(* Logix 5000 project; controller LinePLC1 vendor 1 type 14 code 154 rev 32.11; software revision 32.03 *)

TASK MainTask (continuous, watchdog 500 ms) : MainProgram

MODULES
   Local : vendor 1 type 14 code 154 (PointIO 0, rev 32.11)
      ISC_CAM_146 : ETHERNET-MODULE (Ethernet 192.168.1.146, rev 1.1, Output RPI 10 ms)   // isc-camxb145150d
           ISC_CAM_146:I.Data[1].5   // Status of photoeye Product Sensor 2 (Optional)
           ISC_CAM_146:I.Data[1].2   // Belt detected to move too slow (and not stopped)
           ISC_CAM_146:I.Data[13].0   // Parameter read succesfully
           ISC_CAM_146:I.Data[14]   // Parameter data register High Word
           ISC_CAM_146:I.Data[15]   // Parameter data register Low Word
           ISC_CAM_146:I.Data[1].0   // Line controller PLC indicated the drive motor is running, but the encoder does not detect motion
           ISC_CAM_146:I.Data[1].1   // Line controller PLC indicates the drive motor is off, but the encoder detects belt motion
           ISC_CAM_146:I.Data[1].10   // Too much or too low voltage from power supply
           ISC_CAM_146:I.Data[1].11   // Too much or too little current draw (indicates short or cable disconnected)
           ISC_CAM_146:I.Data[1].7   // Peg sensor blocked continuously with belt moving
           ISC_CAM_146:I.Data[1].3   // Belt detected to move too fast
           ISC_CAM_146:I.Data[1].4   // Status of photoeye Product Sensor 1
           ISC_CAM_146:I.Data[1].6   // Status of photoeye Product Sensor 3 (Optional)
           ISC_CAM_146:I.Data[1].8   // Peg not seen while expected
           ISC_CAM_146:I.Data[20]   // ActivationCount MSW - Cumulative number of activations divert zone 0
           ISC_CAM_146:I.Data[22]   // ActivationCount MSW - Cumulative number of activations divert zone 1
           ISC_CAM_146:I.Data[24]   // ActivationCount MSW - Cumulative number of activations divert zone 2
           ISC_CAM_146:I.Data[3]   // ProductsOnBelt - Count of current products on the belt (Optional in V1 scope)
           ISC_CAM_146:I.Data[0].1   // SystemReady
           ISC_CAM_146:I.Data[13]   // Parameter Status
           ISC_CAM_146:I.Data[18]   // BeltTravelDistance MSW
           ISC_CAM_146:I.Data[19]   // BeltTravelDistance LSW
           ISC_CAM_146:I.Data[30]   // GapToSmallCount MSW - Cumulative number a too small gap was detected
           ISC_CAM_146:I.Data[13].3   // Parameter value is out of range
           ISC_CAM_146:I.Data[13].2   // Parameter number not exist or read only
           ISC_CAM_146:I.Data[1].9   // Gap for next product
           ISC_CAM_146:I.Data[10]   // Uptime LSW - Time since the ISC is powered on
           ISC_CAM_146:I.Data[12]   // Parameter number feedback
           ISC_CAM_146:I.Data[13].1   // Parameter write succesfully
           ISC_CAM_146:I.Data[9]   // Uptime MSW - Time since the ISC is powered on
           ISC_CAM_146:I.Data[0].8   // EncoderStatus
           ISC_CAM_146:I.Data[21]   // ActivationCount LSW
           ISC_CAM_146:I.Data[16]   // BeltRunTime MSW
           ISC_CAM_146:I.Data[1].12   // IO-Link error port C0
           ISC_CAM_146:I.Data[1].13   // IO-Link error port C1
           ISC_CAM_146:I.Data[1].14   // IO-Link error port C2
           ISC_CAM_146:I.Data[1].15   // IO-Link error port C3
           ISC_CAM_146:I.Data[27]   // ProductCount LSW
           ISC_CAM_146:I.Data[34]   // PeakAcceleration
           ISC_CAM_146:I.Data[17]   // BeltRunTime LSW
           ISC_CAM_146:I.Data[1]   // Fault Code Word 1
           ISC_CAM_146:I.Data[2]   // Fault Code Word 2
           ISC_CAM_146:I.Data[0]   // Status
           ISC_CAM_146:I.Data[5]   // BeltSpeed - Current speed of the belt
           ISC_CAM_146:I.Data[6]   // BeltAcceleration - Acceleration speed of the belt
           ISC_CAM_146:I.Data[7]   // IOStatus - Active status of all inputs connected
           ISC_CAM_146:I.Data[0].0   // Life_Bit
           ISC_CAM_146:I.Data[32]   // FaultCount
           ISC_CAM_146:I.Data[29]   // StartStops LSW
           ISC_CAM_146:I.Data[23]   // ActivationCount LSW
           ISC_CAM_146:I.Data[25]   // ActivationCount LSW
           ISC_CAM_146:I.Data[33]   // MaxBeltSpeed
           ISC_CAM_146:I.Data[4]   // Troughput - Products per time unit on DPE (Optional in V1 scope)
           ISC_CAM_146:I.Data[28]   // StartStops MSW - Cumulative number of start stops of the belt
           ISC_CAM_146:I.Data[26]   // ProductCount MSW - Cumulative number of products on the belt
           ISC_CAM_146:I.Data[31]   // GapToSmallCount LSW
           ISC_CAM_146:I.Data[35]   // PeakDecceleration
           ISC_CAM_146:I.Data[0].4   // Error
           ISC_CAM_146:O.Data[1]   // Divert destination of the next product that will be arriving on the belt
           ISC_CAM_146:O.Data[2]   // RunMode
           ISC_CAM_146:O.Data[13]   // Read/Whrite Parameter
           ISC_CAM_146:O.Data[0].1   // BeltRunning
           ISC_CAM_146:O.Data[7]   // DestinationEnableDisable
           ISC_CAM_146:O.Data[3]   // ProductCountExit0
           ISC_CAM_146:O.Data[13].1   // Whrite Parameter
           ISC_CAM_146:O.Data[4]   // ProductCountExit1
           ISC_CAM_146:O.Data[0]   // Status
           ISC_CAM_146:O.Data[5]   // ProductCountExit2
           ISC_CAM_146:O.Data[0].0   // Life_Bit
           ISC_CAM_146:O.Data[12]   // Parameter number
           ISC_CAM_146:O.Data[13].0   // Read Parameter
           ISC_CAM_146:O.Data[14]   // Parameter Data MSW
           ISC_CAM_146:O.Data[0].7   // Reset_Error
           ISC_CAM_146:O.Data[15]   // Parameter Data LSW
           ISC_CAM_146:O.Data[6]   // ProductCountExit3
      ISC_CAM_145 : ETHERNET-MODULE (Ethernet 192.168.1.145, rev 1.1, Output RPI 10 ms)   // isc-camxb145150d
           ISC_CAM_145:I.Data[13].0   // Parameter read succesfully
           ISC_CAM_145:I.Data[14]   // Parameter data register High Word
           ISC_CAM_145:I.Data[15]   // Parameter data register Low Word
           ISC_CAM_145:I.Data[1].0   // Line controller PLC indicated the drive motor is running, but the encoder does not detect motion
           ISC_CAM_145:I.Data[1].1   // Line controller PLC indicates the drive motor is off, but the encoder detects belt motion
           ISC_CAM_145:I.Data[1].10   // Too much or too low voltage from power supply
           ISC_CAM_145:I.Data[1].11   // Too much or too little current draw (indicates short or cable disconnected)
           ISC_CAM_145:I.Data[1].2   // Belt detected to move too slow (and not stopped)
           ISC_CAM_145:I.Data[1].3   // Belt detected to move too fast
           ISC_CAM_145:I.Data[1].4   // Status of photoeye Product Sensor 1
           ISC_CAM_145:I.Data[1].5   // Status of photoeye Product Sensor 2 (Optional)
           ISC_CAM_145:I.Data[1].6   // Status of photoeye Product Sensor 3 (Optional)
           ISC_CAM_145:I.Data[1].7   // Peg sensor blocked continuously with belt moving
           ISC_CAM_145:I.Data[1].8   // Peg not seen while expected
           ISC_CAM_145:I.Data[20]   // ActivationCount MSW - Cumulative number of activations divert zone 0
           ISC_CAM_145:I.Data[22]   // ActivationCount MSW - Cumulative number of activations divert zone 1
           ISC_CAM_145:I.Data[13]   // Parameter Status
           ISC_CAM_145:I.Data[24]   // ActivationCount MSW - Cumulative number of activations divert zone 2
           ISC_CAM_145:I.Data[27]   // ProductCount LSW
           ISC_CAM_145:I.Data[3]   // ProductsOnBelt - Count of current products on the belt (Optional in V1 scope)
           ISC_CAM_145:I.Data[13].3   // Parameter value is out of range
           ISC_CAM_145:I.Data[34]   // PeakAcceleration
           ISC_CAM_145:I.Data[13].2   // Parameter number not exist or read only
           ISC_CAM_145:I.Data[18]   // BeltTravelDistance MSW
           ISC_CAM_145:I.Data[19]   // BeltTravelDistance LSW
           ISC_CAM_145:I.Data[30]   // GapToSmallCount MSW - Cumulative number a too small gap was detected
           ISC_CAM_145:I.Data[0].0   // Life_Bit
           ISC_CAM_145:I.Data[0].1   // SystemReady
           ISC_CAM_145:I.Data[5]   // BeltSpeed - Current speed of the belt
           ISC_CAM_145:I.Data[0]   // Status
           ISC_CAM_145:I.Data[32]   // FaultCount
           ISC_CAM_145:I.Data[1].9   // Gap for next product
           ISC_CAM_145:I.Data[10]   // Uptime LSW - Time since the ISC is powered on
           ISC_CAM_145:I.Data[12]   // Parameter number feedback
           ISC_CAM_145:I.Data[13].1   // Parameter write succesfully
           ISC_CAM_145:I.Data[9]   // Uptime MSW - Time since the ISC is powered on
           ISC_CAM_145:I.Data[0].8   // EncoderStatus
           ISC_CAM_145:I.Data[16]   // BeltRunTime MSW
           ISC_CAM_145:I.Data[17]   // BeltRunTime LSW
           ISC_CAM_145:I.Data[1].12   // IO-Link error port C0
           ISC_CAM_145:I.Data[1].13   // IO-Link error port C1
           ISC_CAM_145:I.Data[1].14   // IO-Link error port C2
           ISC_CAM_145:I.Data[1].15   // IO-Link error port C3
           ISC_CAM_145:I.Data[21]   // ActivationCount LSW
           ISC_CAM_145:I.Data[23]   // ActivationCount LSW
           ISC_CAM_145:I.Data[25]   // ActivationCount LSW
           ISC_CAM_145:I.Data[1]   // Fault Code Word 1
           ISC_CAM_145:I.Data[31]   // GapToSmallCount LSW
           ISC_CAM_145:I.Data[2]   // Fault Code Word 2
           ISC_CAM_145:I.Data[4]   // Troughput - Products per time unit on DPE (Optional in V1 scope)
           ISC_CAM_145:I.Data[6]   // BeltAcceleration - Acceleration speed of the belt
           ISC_CAM_145:I.Data[7]   // IOStatus - Active status of all inputs connected
           ISC_CAM_145:I.Data[0].4   // Error
           ISC_CAM_145:I.Data[26]   // ProductCount MSW - Cumulative number of products on the belt
           ISC_CAM_145:I.Data[29]   // StartStops LSW
           ISC_CAM_145:I.Data[28]   // StartStops MSW - Cumulative number of start stops of the belt
           ISC_CAM_145:I.Data[33]   // MaxBeltSpeed
           ISC_CAM_145:I.Data[35]   // PeakDecceleration
           ISC_CAM_145:O.Data[13]   // Read/Whrite Parameter
           ISC_CAM_145:O.Data[1]   // Divert destination of the next product that will be arriving on the belt
           ISC_CAM_145:O.Data[12]   // Parameter number
           ISC_CAM_145:O.Data[0].1   // BeltRunning
           ISC_CAM_145:O.Data[13].1   // Whrite Parameter
           ISC_CAM_145:O.Data[0].7   // Reset_Error
           ISC_CAM_145:O.Data[2]   // RunMode
           ISC_CAM_145:O.Data[7]   // DestinationEnableDisable
           ISC_CAM_145:O.Data[3]   // ProductCountExit0
           ISC_CAM_145:O.Data[0]   // Status
           ISC_CAM_145:O.Data[0].0   // Life_Bit
           ISC_CAM_145:O.Data[4]   // ProductCountExit1
           ISC_CAM_145:O.Data[5]   // ProductCountExit2
           ISC_CAM_145:O.Data[6]   // ProductCountExit3
           ISC_CAM_145:O.Data[13].0   // Read Parameter
           ISC_CAM_145:O.Data[14]   // Parameter Data MSW
           ISC_CAM_145:O.Data[15]   // Parameter Data LSW
      Discrete_IO : Embedded (PointIO 1, rev 32.11, Output RPI 20 ms)
      DO_002 : 1734-OB8E (PointIO 3, rev 3.1, Output RPI 20 ms)
      DO_001 : 1734-OB8E (PointIO 2, rev 3.1, Output RPI 20 ms)
END_MODULES

TYPE dt_Constant :   // Constants
STRUCT
   ParameterNr : DINT;
   RecipeNr : DINT;
END_STRUCT
END_TYPE

TYPE dt_DTL :   // An operand of data type DTL has a length of 12 bytes and stores date and time information in a predefined structure.
STRUCT
   Year : INT;   // Year - 1970 to 2262
   Month : SINT;   // Month - 0 to 12
   Day : SINT;   // Day - 1 to 31
   Weekday : SINT;   // Weekday - 1(Sunday) to 7(Saturday) The weekday is not considered in the value entry.
   Hour : SINT;   // Hour - 0 to 23
   Minute : SINT;   // Minute - 0 to 59
   Second : SINT;   // Second - 0 to 59
   Nanosecond : DINT;   // Nanosecond - 0 to 999999999
END_STRUCT
END_TYPE

TYPE dt_General_HMI :   // General HMI
STRUCT
   GeneralDateTimePLC : dt_DTL;
   GeneralHmiSNPointer : INT[5];
   GeneralHMIScreenNumber : INT;
   GeneralFaultBits : INT[8];
   GeneralFaultGroupBits : INT;
   GeneralFault : BOOL;
   GeneralAlarmBtnCol : INT;
   GeneralResetBtnCmd : BOOL;
   AlarmBtnCol : INT;
   MaintenanceBtnCol : INT;
END_STRUCT
END_TYPE

TYPE dt_Global :   // Global
STRUCT
   InitRecipe : BOOL;
   MyMODE : DINT;
   returnValue : INT;
   myState : BOOL[1024];
END_STRUCT
END_TYPE

TYPE dt_ISC_CAM_Alarms :
STRUCT
   CommsAlarm : BOOL;   // Communication to ISC not healthy.
   Fault8Alarm : BOOL;   // Peg not seen when expected
   Fault9Alarm : BOOL;   // Gap for next product
   Fault10Alarm : BOOL;   // Too much or too low voltage from power supply
   Fault11Alarm : BOOL;   // IO Current fault, input too high or too low (indicates short or cable disconnected)
   Fault12Alarm : BOOL;   // IO-Link error port C0
   Fault13Alarm : BOOL;   // IO-Link error port C1
   Fault14Alarm : BOOL;   // IO-Link error port C2
   Fault15Alarm : BOOL;   // IO-Link error port C3
   Fault0Alarm : BOOL;   // Line controller PLC indicated the motor is running. But the encoder does not detect motion
   Fault1Alarm : BOOL;   // Peg sensor blocked continuously with belt moving
   Fault2Alarm : BOOL;   // Status of photoeye Product Sensor 3 (optional)
   Fault3Alarm : BOOL;   // Status of photoeye Product Sensor 2 (optional)
   Fault4Alarm : BOOL;   // Status of photoeye Product Sensor 1
   Fault5Alarm : BOOL;   // Belt detected to move too fast
   Fault6Alarm : BOOL;   // Belt detected to move too slow (and not stopped)
   Fault7Alarm : BOOL;   // Line controller PLC indicates the drive motor is off, but the encoder detects belt motion
END_STRUCT
END_TYPE

TYPE dt_ISC_CAM_Comm :
STRUCT
   DataIn : DINT[48];
   TempDataIn : dt_ISCCAM_IO_IN;
   DataOut : DINT[16];
   TempDataOut : dt_ISCCAM_IO_OUT;
   CommHealthy : BOOL;
   CommStatus : INT;
   ConnectionStatus : INT;
   Comms : FB_ISCCAM_Comm;
   Alarms : FB_ISC_Alarms;
   IOConversion : FB_IO_Conversion;
   tempIn : DINT[48];
   tempOut : DINT[48];
END_STRUCT
END_TYPE

TYPE dt_ISC_CAM_FaultCodes :
STRUCT
   FaultCode8 : BOOL;   // Peg not seen when expected
   FaultCode9 : BOOL;   // Gap for next product
   FaultCode10 : BOOL;   // Too much or too low voltage from power supply
   FaultCode11 : BOOL;   // IO Current fault, input too high or too low (indicates short or cable disconnected)
   FaultCode12 : BOOL;   // IO-Link error port C0
   FaultCode13 : BOOL;   // IO-Link error port C1
   FaultCode14 : BOOL;   // IO-Link error port C2
   FaultCode15 : BOOL;   // IO-Link error port C3
   FaultCode0 : BOOL;   // Line controller PLC indicated the motor is running. But the encoder does not detect motion
   FaultCode1 : BOOL;   // Peg sensor blocked continuously with belt moving
   FaultCode2 : BOOL;   // Status of photoeye Product Sensor 3 (optional)
   FaultCode3 : BOOL;   // Status of photoeye Product Sensor 2 (optional)
   FaultCode4 : BOOL;   // Status of photoeye Product Sensor 1
   FaultCode5 : BOOL;   // Belt detected to move too fast
   FaultCode6 : BOOL;   // Belt detected to move too slow (and not stopped)
   FaultCode7 : BOOL;   // Line controller PLC indicates the drive motor is off, but the encoder detects belt motion
   FaultCode24 : BOOL;
   FaultCode25 : BOOL;
   FaultCode26 : BOOL;
   FaultCode27 : BOOL;
   FaultCode28 : BOOL;
   FaultCode29 : BOOL;
   FaultCode30 : BOOL;
   FaultCode31 : BOOL;
   FaultCode16 : BOOL;
   FaultCode17 : BOOL;
   FaultCode18 : BOOL;
   FaultCode19 : BOOL;
   FaultCode20 : BOOL;
   FaultCode21 : BOOL;
   FaultCode22 : BOOL;
   FaultCode23 : BOOL;
END_STRUCT
END_TYPE

TYPE dt_ISC_CAM_IOStatus :
STRUCT
   IOStatus8 : BOOL;
   IOStatus9 : BOOL;
   IOStatus10 : BOOL;
   IOStatus11 : BOOL;
   IOStatus12 : BOOL;
   IOStatus13 : BOOL;
   IOStatus14 : BOOL;
   IOStatus15 : BOOL;
   IOStatus0 : BOOL;
   IOStatus1 : BOOL;   // Product sensor
   IOStatus2 : BOOL;   // Peg sensor diver 1 (AIM only)
   IOStatus3 : BOOL;   // Valve divert 1
   IOStatus4 : BOOL;   // Peg sensor diver 2 (AIM only)
   IOStatus5 : BOOL;   // Valve divert 2
   IOStatus6 : BOOL;   // Discrete diver signal
   IOStatus7 : BOOL;
END_STRUCT
END_TYPE

TYPE dt_ISC_CAM_Maintenance :
STRUCT
   Threshold : DINT[16];
   Maintenance : FB_ISC_CAM_Maintenance[16];
END_STRUCT
END_TYPE

TYPE dt_ISC_CAM_Receive :
STRUCT
   W0 : dt_ISC_CAM_RECEIVE_W0;
   W1W2_Faultcode : DINT;
   W3_ProductsOnBelt : INT;
   W4_ThroughPut : INT;
   W5_Beltspeed : INT;
   W6_BeltAcceleration : INT;
   W7_IOStatus : INT;
   W8 : INT;
   W9_PowerOn_MSW : INT;
   W10_PowerOn_LSW : INT;
   W11 : INT;
   W12_ParameterNumberFeedback : INT;
   W13 : dt_ISC_CAM_RECEIVE_W13;
   W14_ParameterDataRegisterHighWord : INT;
   W15_ParameterDataRegisterLowWor : INT;
   W16_BeltRunTime_MSW : INT;
   W17_BeltRunTime_LSW : INT;
   W18BeltTravelDistance_MSW : INT;
   W19BeltTravelDistance_LSW : INT;
   W20ActivationCount_Zone0_MSW : INT;
   W21ActivationCount_Zone0_LSW : INT;
   W22ActivationCount_Zone1_MSW : INT;
   W23ActivationCount_Zone1_LSW : INT;
   W24ActivationCount_Zone2_MSW : INT;
   W25ActivationCount_Zone2_LSW : INT;
   W26ProductCount_MSW : INT;
   W27ProductCount_LSW : INT;
   W28StartStops_MSW : INT;
   W29StartStops_LSW : INT;
   W30GapToSmallCount_MSW : INT;
   W31GapToSmallCount_LSW : INT;
   W32FaultCount : INT;
   W33MaxBeltSpeed : INT;
   W34PeakAcceleration : INT;
   W35PeakDeceleration : INT;
END_STRUCT
END_TYPE

TYPE dt_ISC_CAM_RECEIVE_W0 :
STRUCT
   Bit8 : BOOL;
   Bit9 : BOOL;
   Bit10 : BOOL;
   Bit11 : BOOL;
   Bit12 : BOOL;
   Bit13 : BOOL;
   Bit14 : BOOL;
   Bit15 : BOOL;
   Bit0LifeBit : BOOL;
   Bit1SystemReady : BOOL;
   Bit2 : BOOL;
   Bit3 : BOOL;
   Bit4Error : BOOL;
   Bit5 : BOOL;
   Bit6 : BOOL;
   Bit7 : BOOL;
END_STRUCT
END_TYPE

TYPE dt_ISC_CAM_RECEIVE_W13 :
STRUCT
   Bit8 : BOOL;
   Bit9 : BOOL;
   Bit10 : BOOL;
   Bit11 : BOOL;
   Bit12 : BOOL;
   Bit13 : BOOL;
   Bit14 : BOOL;
   Bit15 : BOOL;
   Bit0ParameterReadSuccesful : BOOL;
   Bit1ParameterWriteSucceful : BOOL;
   Bit2ParameterNumberNotExistOrReadOnly : BOOL;
   Bit3ParameterValueIsOutOfRange : BOOL;
   Bit4 : BOOL;
   Bit5 : BOOL;
   Bit6 : BOOL;
   Bit7 : BOOL;
END_STRUCT
END_TYPE

TYPE dt_ISC_CAM_Send :
STRUCT
   W0 : dt_ISC_CAM_SEND_W0;
   W1_DivertDestination : INT;
   W2_RunMode : INT;
   W3_ProductCountExit0 : INT;
   W4_ProductCountExit1 : INT;
   W5_ProductCountExit2 : INT;
   W6_ProductCountExit3 : INT;
   W7 : dt_ISCCAM_Send_W7;
   W8 : INT;
   W9 : INT;
   W10 : INT;
   W11 : INT;
   W12_ParameterNumberForReadWriteAccess : INT;
   W13 : dt_ISCCAM_Send_W13;
   W14_ParameterDataRegisterHighWord : INT;
   W15_ParameterDataRegisterLowWord : INT;
END_STRUCT
END_TYPE

TYPE dt_ISC_CAM_SEND_W0 :
STRUCT
   Bit8 : BOOL;
   Bit9 : BOOL;
   Bit10 : BOOL;
   Bit11 : BOOL;
   Bit12 : BOOL;
   Bit13ProductsFromInfeed2 : BOOL;
   Bit14 : BOOL;
   Bit15 : BOOL;
   Bit0LifeBit : BOOL;
   Bit1MotorRunning : BOOL;
   Bit2 : BOOL;
   Bit3 : BOOL;
   Bit4 : BOOL;
   Bit5 : BOOL;
   Bit6 : BOOL;
   Bit7Reset_Error : BOOL;
END_STRUCT
END_TYPE

TYPE dt_ISC_CAM_Status :
STRUCT
   Status : dt_ISCCAM_Stat;
   Command : dt_ISCCAM_Cmd;
   Parameter : dt_ISCCAM_Parameter;
   DataCollection : dt_ISCCAM_Datacollection;
END_STRUCT
END_TYPE

TYPE dt_ISCCAM :   // ISC-CAM
STRUCT
   Command : dt_ISCCAM_Cmd;
   Status : dt_ISCCAM_Stat;
   Parameter : dt_ISCCAM_Parameter;
   Datacollection : dt_ISCCAM_Datacollection;
END_STRUCT
END_TYPE

TYPE dt_ISCCAM_Cmd :   // ISC-CAM Cmd
STRUCT
   LifeBit : BOOL;   // Lifebit
   Reset_Error : BOOL;   // Reset error
   MotorRunning : BOOL;   // Motor running
   ProductsFromInfeed2 : BOOL;   // Products from infeed 2
   AssignDestination : INT;   // Assign destination
   ExternalModel : BOOL;   // External model
   Exit1BalancingSet : INT;   // Set balancing exit 1
   Exit2BalancingSet : INT;   // Set balancing exit 2
   Exit3BalancingSet : INT;   // Set balancing exit 3
   EndBalancingSet : INT;   // Set balancing end
   DES_Enable1 : BOOL;   // Enable destination 1
   DES_Enable2 : BOOL;   // Enable destination 2
   DES_Enable3 : BOOL;   // Enable destination 3
END_STRUCT
END_TYPE

TYPE dt_ISCCAM_Datacollection :   // ISC-CAM Datacollection
STRUCT
   BeltRunTime : DINT;   // Cumulative time the belt is moving [min]
   BeltTravelDistance : DINT;   // Cumulative distance the belt has traveled [m]
   ActivationCount_Zone_0 : DINT;   // Cumulative number of activations divert zone 0
   ActivationCount_Zone_1 : DINT;   // Cumulative number of activations divert zone 1
   ActivationCount_Zone_2 : DINT;   // Cumulative number of activations divert zone 2
   ProductCount : DINT;   // Cumulative number of products on the belt
   StartStops : DINT;   // Cumulative number of start stops of the belt
   GapToSmallCount : DINT;   // Cumulative number a too small gap was detected
   FaultCount : INT;   // A counter that keeps track of how many faults were detected
   MaxBeltSpeed : INT;   // The maximum belt speed that has been detected [m/min]
   PeakAcceleration : INT;   // Peak acceleration [m/min2]
   PeakDecceleration : INT;   // Peak decceleration [m/min2]
END_STRUCT
END_TYPE

TYPE dt_ISCCAM_FaultCode :   // ISC-CAM Fault Code
STRUCT
   FaultCode : BOOL[32];   // FaultCode
   FaultCode00 : BOOL;   // Line controller PLC indicated the drive motor is running, but the encoder does not detect motion
   FaultCode01 : BOOL;   // Line controller PLC indicates the drive motor is off, but the encoder detects belt motion
   FaultCode02 : BOOL;   // Belt detected to move too slow (and not stopped)
   FaultCode03 : BOOL;   // Belt detected to move too fast
   FaultCode04 : BOOL;   // Status of photoeye Product Sensor 1
   FaultCode05 : BOOL;   // Status of photoeye Product Sensor 2 (Optional)
   FaultCode06 : BOOL;   // Status of photoeye Product Sensor 3 (Optional)
   FaultCode07 : BOOL;   // Peg sensor blocked continuously with belt moving
   FaultCode08 : BOOL;   // Peg not seen when expected
   FaultCode09 : BOOL;   // Gap for next product
   FaultCode10 : BOOL;   // Too much or too low voltage from power supply
   FaultCode11 : BOOL;   // IO Current fault. Input too high or too low (indicates short or cable disconnected)
   FaultCode12 : BOOL;   // IO-Link error port C0
   FaultCode13 : BOOL;   // IO-Link error port C1
   FaultCode14 : BOOL;   // IO-Link error port C2
   FaultCode15 : BOOL;   // IO-Link error port C3
   FaultCode16 : BOOL;
   FaultCode17 : BOOL;
   FaultCode18 : BOOL;
   FaultCode19 : BOOL;
   FaultCode20 : BOOL;
   FaultCode21 : BOOL;
   FaultCode22 : BOOL;
   FaultCode23 : BOOL;
   FaultCode24 : BOOL;
   FaultCode25 : BOOL;
   FaultCode26 : BOOL;
   FaultCode27 : BOOL;
   FaultCode28 : BOOL;
   FaultCode29 : BOOL;
   FaultCode30 : BOOL;
   FaultCode31 : BOOL;
END_STRUCT
END_TYPE

TYPE dt_ISCCAM_HMI :   // Machine 001 HMI
STRUCT
   FaultBits : dt_ISC_CAM_Alarms;
   Fault : BOOL;
   MaintenanceCounters : dt_ISCCAM_Maintenance;
END_STRUCT
END_TYPE

TYPE dt_ISCCAM_IO_IN :
STRUCT
   W1 : DINT;
   W2 : DINT;
   W3 : DINT;
   W4 : DINT;
   W5 : DINT;
   W6 : DINT;
   W7 : DINT;
   W8 : DINT;
   W9 : DINT;
   W10 : DINT;
   W11 : DINT;
   W12 : DINT;
   W13 : DINT;
   W14 : DINT;
   W15 : DINT;
   W16 : DINT;
   W17 : DINT;
   W18 : DINT;
   W19 : DINT;
   W20 : DINT;
   W21 : DINT;
   W22 : DINT;
   W23 : DINT;
   W24 : DINT;
   W25 : DINT;
   W26 : DINT;
   W27 : DINT;
   W28 : DINT;
   W29 : DINT;
   W30 : DINT;
   W31 : DINT;
   W32 : DINT;
   W33 : DINT;
   W34 : DINT;
   W35 : DINT;
   W36 : DINT;
   W37 : DINT;
   W38 : DINT;
   W39 : DINT;
   W40 : DINT;
   W41 : DINT;
   W42 : DINT;
   W43 : DINT;
   W44 : DINT;
   W45 : DINT;
   W46 : DINT;
   W47 : DINT;
   W48 : DINT;
END_STRUCT
END_TYPE

TYPE dt_ISCCAM_IO_OUT :
STRUCT
   W1 : DINT;
   W2 : DINT;
   W3 : DINT;
   W4 : DINT;
   W5 : DINT;
   W6 : DINT;
   W7 : DINT;
   W8 : DINT;
   W9 : DINT;
   W10 : DINT;
   W11 : DINT;
   W12 : DINT;
   W13 : DINT;
   W14 : DINT;
   W15 : DINT;
   W16 : DINT;
END_STRUCT
END_TYPE

TYPE dt_ISCCAM_Maintenance :
STRUCT
   Counters : dt_ISCCAM_MaintenanceCounter[16];
END_STRUCT
END_TYPE

TYPE dt_ISCCAM_MaintenanceCounter :
STRUCT
   Reset : BOOL;   // Reset warning
   WarningBit : BOOL;   // Warning active
   MaintenanceThreshold : DINT;   // Threshold to create warning
   MaintenanceCountUntilNextMaintenance : DINT;   // Count until next maintenance
END_STRUCT
END_TYPE

TYPE dt_ISCCAM_Parameter :   // ISC-CAM Parameter
STRUCT
   Cmd : dt_ISCCAM_Parameter_Cmd;
   Stat : dt_ISCCAM_Parameter_Stat;
END_STRUCT
END_TYPE

TYPE dt_ISCCAM_Parameter_Cmd :   // ISC-CAM Parameter Cmd
STRUCT
   ParameterNumber : INT;   // Parameter number f or read / write access.
   ParameterData : DINT;   // Parameter data f or write access.
   ReadTrigger : BOOL;   // Read trigger.
   WriteTrigger : BOOL;   // Write trigger.
END_STRUCT
END_TYPE

TYPE dt_ISCCAM_Parameter_Stat :   // ISC-CAM Parameter Stat
STRUCT
   ParameterNumber : INT;   // Parameter number feedback
   ParameterData : DINT;   // Parameter data
   ParameterReadSuccessfully : BOOL;   // Parameter read successfully
   ParameterWriteSuccessfully : BOOL;   // Parameter write successfully
   ParameterNumberNotExistReadOnly : BOOL;   // Parameter number does not exist or is read only
   ParameterValueOutOfRange : BOOL;   // Parameter value out of range
END_STRUCT
END_TYPE

TYPE dt_ISCCAM_PI :   // ISC-CAM PI
STRUCT
   Status : dt_ISCCAM_PI_Status;
   DataCollection1 : dt_ISCCAM_PI_DataCollection_1;
   DataCollection2 : dt_ISCCAM_PI_DataCollection_2;
END_STRUCT
END_TYPE

TYPE dt_ISCCAM_PI_DataCollection_1 :   // ISC-CAM PI Data Collection 1
STRUCT
   BeltRunTime_MSW : INT;   // Cumulative time the belt is moving [min] HiWord
   BeltRunTime_LSW : INT;   // Cumulative time the belt is moving [min] LoWord
   BeltTravelDistance_MSW : INT;   // Cumulative distance the belt has traveled [m] HiWord
   BeltTravelDistance_LSW : INT;   // Cumulative distance the belt has traveled [m] LoWord
   ActivationCount_Zone0_MSW : INT;   // Cumulative number of activations divert zone 0 HiWord
   ActivationCount_Zone0_LSW : INT;   // Cumulative number of activations divert zone 0 LoWord
   ActivationCount_Zone1_MSW : INT;   // Cumulative number of activations divert zone 1 HiWord
   ActivationCount_Zone1_LSW : INT;   // Cumulative number of activations divert zone 1 LoWord
   ActivationCount_Zone2_MSW : INT;   // Cumulative number of activations divert zone 2 HiWord
   ActivationCount_Zone2_LSW : INT;   // Cumulative number of activations divert zone 2 LoWord
   ProductCount_MSW : INT;   // Cumulative number of products on the belt HiWord
   ProductCount_LSW : INT;   // Cumulative number of products on the belt LoWord
   StartStops_MSW : INT;   // Cumulative number of start stops of the belt HiWord
   StartStops_LSW : INT;   // Cumulative number of start stops of the belt LoWord
   GapToSmallCount_MSW : INT;   // Cumulative number a too small gap was detected HiWord
   GapToSmallCount_LSW : INT;   // Cumulative number a too small gap was detected LoWord
END_STRUCT
END_TYPE

TYPE dt_ISCCAM_PI_DataCollection_2 :   // ISC-CAM PI Data Collection 2
STRUCT
   FaultCount : INT;   // A counter that keeps track of how many faults were detected
   MaxBeltSpeed : INT;   // The maximum belt speed that has been detected [m/min]
   PeakAcceleration : INT;   // Peak acceleration [m/min2]
   PeakDecceleration : INT;   // Peak decceleration [m/min2]
END_STRUCT
END_TYPE

TYPE dt_ISCCAM_PI_Status :   // ISC-CAM PI Status
STRUCT
   Life_Bit : BOOL;   // Life bit / Heartbeat / Watchdog
   SystemReady : BOOL;   // System Ready (no fault)
   W0b2 : BOOL;
   W0b3 : BOOL;
   Error : BOOL;   // Error in Machine
   W0b4 : BOOL;
   W0b5 : BOOL;
   W0b6 : BOOL;
   W0b7 : BOOL;
   EncoderStatus : BOOL;   // Belt encoder pulses
   W0b9 : BOOL;
   W0b10 : BOOL;
   W0b11 : BOOL;
   W0b12 : BOOL;
   W0b13 : BOOL;
   W0b14 : BOOL;
   W0b15 : BOOL;
END_STRUCT
END_TYPE

TYPE dt_ISCCAM_PO :   // ISC-CAM PO
STRUCT
   Command : dt_ISCCAM_PO_Command;
END_STRUCT
END_TYPE

TYPE dt_ISCCAM_PO_Command :   // ISC_CAM_PO_Command
STRUCT
   Life_Bit : BOOL;   // Life bit
   MotorRunning : BOOL;   // Motor is running
   W0b2 : BOOL;
   W0b3 : BOOL;
   W0b4 : BOOL;
   W0b5 : BOOL;
   W0b6 : BOOL;
   Reset_Error : BOOL;   // Reset all errors
   W0b8 : BOOL;
   W0b9 : BOOL;
   W0b10 : BOOL;
   W0b11 : BOOL;
   W0b12 : BOOL;
   ProductsFromInfeed2 : BOOL;   // Products from infeed 2
   W0b14 : BOOL;
   W0b15 : BOOL;
   Divert_destination : INT;   // Divert destination of the next product that will be arriving on the belt (external mode only)
   RunMode : INT;   // Internal mode [0] or external mode [1]
   ProductCountExit0 : INT;   // Number of products to exit (internal mode only)
   ProductCountExit1 : INT;   // Number of products to exit (internal mode only)
   ProductCountExit2 : INT;   // Number of products to exit (internal mode only)
   ProductCountExit3 : INT;   // Number of products to exit (internal mode only)
   Enable_exit_1 : BOOL;   // Destination Enable/Disable
   Enable_exit_2 : BOOL;   // Destination Enable/Disable
   Enable_exit_3 : BOOL;   // Destination Enable/Disable
   W7b3 : BOOL;
   W7b4 : BOOL;
   W7b5 : BOOL;
   W7b6 : BOOL;
   W7b7 : BOOL;
   W8 : INT;
   W9 : INT;
   W10 : INT;
   W11 : INT;
   Parameter_number_for_read_write_access : INT;   // Parameter number
   Read_Parameter : BOOL;   // Read parameter
   Write_Parameter : BOOL;   // Write parameter
   W13b2 : BOOL;
   W13b3 : BOOL;
   W13b4 : BOOL;
   W13b5 : BOOL;
   W13b6 : BOOL;
   W13b7 : BOOL;
   W13b8 : BOOL;
   W13b9 : BOOL;
   W13b10 : BOOL;
   W13b11 : BOOL;
   W13b12 : BOOL;
   W13b13 : BOOL;
   W13b14 : BOOL;
   W13b15 : BOOL;
   Parameter_data_register_High_Word : INT;   // Parameter Data MSW
   Parameter_data_register_Low_Word : INT;   // Parameter Data LSW
END_STRUCT
END_TYPE

TYPE dt_ISCCAM_Send_W13 :
STRUCT
   Bit8 : BOOL;
   Bit9 : BOOL;
   Bit10 : BOOL;
   Bit11 : BOOL;
   Bit12 : BOOL;
   Bit13 : BOOL;
   Bit14 : BOOL;
   Bit15 : BOOL;
   Bit0ReadParameter : BOOL;
   Bit1WriteParameter : BOOL;
   Bit2 : BOOL;
   Bit3 : BOOL;
   Bit4 : BOOL;
   Bit5 : BOOL;
   Bit6 : BOOL;
   Bit7 : BOOL;
END_STRUCT
END_TYPE

TYPE dt_ISCCAM_Send_W7 :
STRUCT
   Bit8 : BOOL;
   Bit9 : BOOL;
   Bit10 : BOOL;
   Bit11 : BOOL;
   Bit12 : BOOL;
   Bit13 : BOOL;
   Bit14 : BOOL;
   Bit15 : BOOL;
   Bit0EnableExit1 : BOOL;
   Bit1EnableExit2 : BOOL;
   Bit2EnableExit3 : BOOL;
   Bit3 : BOOL;
   Bit4 : BOOL;
   Bit5 : BOOL;
   Bit6 : BOOL;
   Bit7 : BOOL;
END_STRUCT
END_TYPE

TYPE dt_ISCCAM_Stat :   // ISC-CAM Stat
STRUCT
   LifeBit : BOOL;   // Lifebit
   SystemReady : BOOL;   // System ready
   Error : BOOL;   // Error
   FaultCode : dt_ISC_CAM_FaultCodes;   // Fault code
   ProductsOnBelt : INT;   // Products on belt
   Throughput : INT;   // Throughput
   BeltSpeed : INT;   // Belt speed
   BeltAcceleration : INT;   // Belt acceleration
   IOstatus : dt_ISC_CAM_IOStatus;   // IO status
   UpTime : DINT;   // Up time
   Alarms : dt_ISC_CAM_Alarms;
END_STRUCT
END_TYPE

TYPE dt_Rec_ISCCAM_Parameter :   // Recipe ISCCAM Parameter
STRUCT
   ID : INT;
   Description : STRING;
END_STRUCT
END_TYPE

TYPE dt_Rec_ISCCAM_Recipe :   // Recipe ISCCAM Recipe
STRUCT
   Header : dt_Rec_ISCCAM_Recipe_Header;
   Machine : dt_Rec_ISCCAM_Recipe_Parameter;
END_STRUCT
END_TYPE

TYPE dt_Rec_ISCCAM_Recipe_Header :   // Recipe ISCCAM Recipe
STRUCT
   Name : STRING;
   Number : DINT;
END_STRUCT
END_TYPE

TYPE dt_Rec_ISCCAM_Recipe_Parameter :   // Recipe ISCCAM Recipe Parameter
STRUCT
   ID : INT;   // Parameter ID.
   Name : STRING;   // Parameter Name.
   Description : STRING;   // Comment.
   Value : DINT;   // Parameter value.
END_STRUCT
END_TYPE

TYPE dt_Rec_M001_Recipe :   // Machine M001 Recipe
STRUCT
   Header : dt_Rec_ISCCAM_Recipe_Header;
   Machine_001 : dt_Rec_Machine_Recipe_Parameter;
END_STRUCT
END_TYPE

TYPE dt_Rec_M002_Recipe :
STRUCT
   Header : dt_Rec_ISCCAM_Recipe_Header;
   Machine_002 : dt_Rec_Machine_Recipe_Parameter;
END_STRUCT
END_TYPE

TYPE dt_Rec_Machine_Recipe_Parameter :
STRUCT
   Parameter : dt_Rec_ISCCAM_Recipe_Parameter[32];
END_STRUCT
END_TYPE

TYPE dt_Rec_Recipe :   // Recipe
STRUCT
   Header : dt_Rec_ISCCAM_Recipe_Header;
   M001 : dt_Rec_M001_Recipe;
   M002 : dt_Rec_M002_Recipe;
END_STRUCT
END_TYPE

TYPE dt_Recipe :   // Recipe
STRUCT
   ParameterList : dt_Rec_ISCCAM_Parameter[14];
   Recipe : dt_Rec_Recipe[4];
END_STRUCT
END_TYPE

ADD_ON_INSTRUCTION FB_2INT_To_DINT   (* revision 1.0, vendor INTRALOX *)
VAR_INPUT
   iINT_MSW : INT; {required}
   iINT_LSW : INT; {required}
END_VAR
VAR_OUTPUT
   qDINT : DINT; {access Read Only, required}
END_VAR
VAR
   sDINT_1 : DINT; {access None}
   sDINT_2 : DINT; {access None}
END_VAR

ROUTINE Logic   (* ladder *)
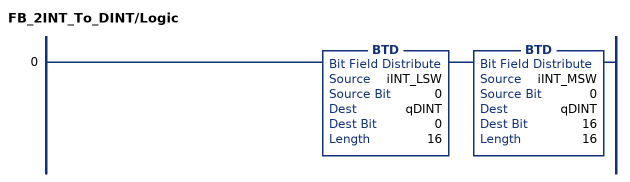
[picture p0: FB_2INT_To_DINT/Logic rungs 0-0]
   0: BTD(iINT_LSW,0,qDINT,0,16)BTD(iINT_MSW,0,qDINT,16,16);
END_ROUTINE
END_ADD_ON_INSTRUCTION

ADD_ON_INSTRUCTION FB_Auxiliary_Sensors   (* revision 1.0, vendor INTRALOX *)
VAR_INPUT
   iPressureSwitch : BOOL := 1; {required}
   iBeltElongationInfeed1 : BOOL := 1; {required}
   iBeltElongationInfeed2 : BOOL := 1; {required}
   iBeltElongationOutfeed1 : BOOL := 1; {required}
   iBeltElongationOutfeed2 : BOOL := 1; {required}
   iJamSensorInfeed : BOOL := 1; {required}
   iJamSensorOutfeed : BOOL := 1; {required}
   iBeltDisengagement : BOOL := 1; {required}
   iDebris : BOOL := 1; {required}
   iReset : BOOL := 1; {required}
END_VAR
VAR_IN_OUT
   oAlarms : BOOL[32]; {required}
END_VAR
VAR_INPUT
   iJamSensor1Time : DINT; {required}   // Time in ms to trigger Jam sensor fault
   iJamSensor2Time : DINT; {access None, required}   // Time in ms to trigger Jam sensor fault
   iBeltRunning : BOOL; {access None, required}   // Belt is running signal
END_VAR
VAR
   JamSensor1Timer : TIMER := (PRE := 2000); {access None}
   JamSensor2Timer : TIMER := (PRE := 2000); {access None}
END_VAR

ROUTINE Logic   (* ladder *)
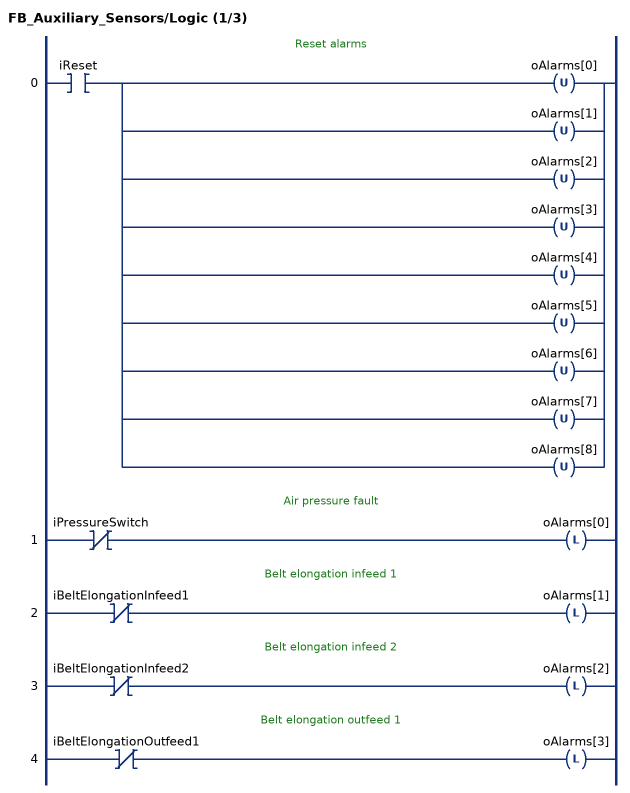
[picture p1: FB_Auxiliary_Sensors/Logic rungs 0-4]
   // Reset alarms
   0: XIC(iReset)[OTU(oAlarms[0]) ,OTU(oAlarms[1]) ,OTU(oAlarms[2]) ,OTU(oAlarms[3]) ,OTU(oAlarms[4]) ,OTU(oAlarms[5]) ,OTU(oAlarms[6]) ,OTU(oAlarms[7]) ,OTU(oAlarms[8]) ];
   // Air pressure fault
   1: XIO(iPressureSwitch)OTL(oAlarms[0]);
   // Belt elongation infeed 1
   2: XIO(iBeltElongationInfeed1)OTL(oAlarms[1]);
   // Belt elongation infeed 2
   3: XIO(iBeltElongationInfeed2)OTL(oAlarms[2]);
   // Belt elongation outfeed 1
   4: XIO(iBeltElongationOutfeed1)OTL(oAlarms[3]);
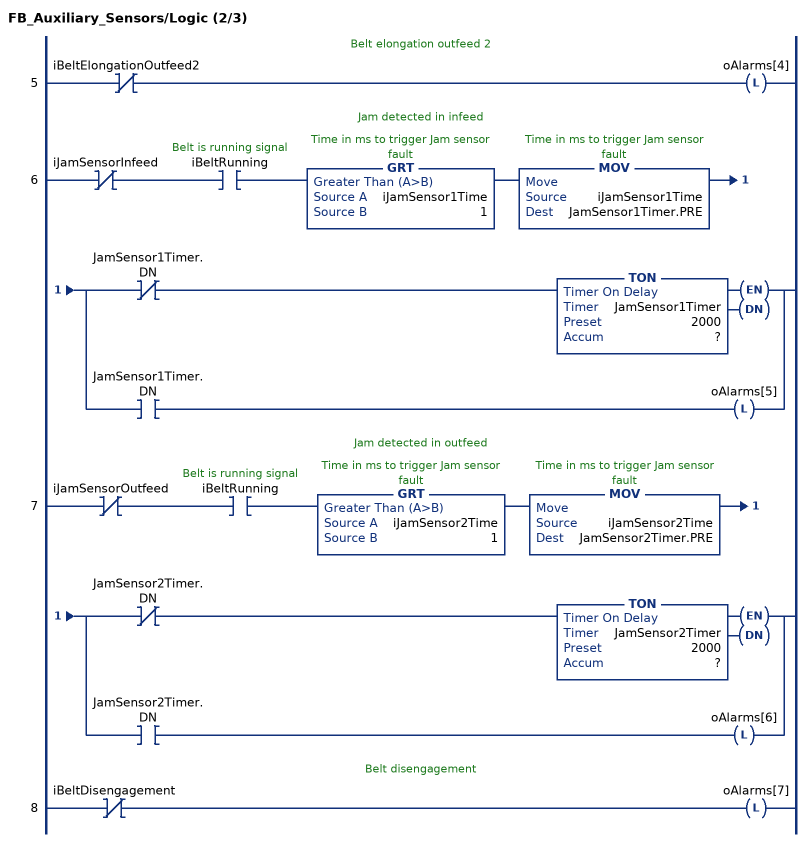
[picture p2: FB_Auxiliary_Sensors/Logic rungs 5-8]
   // Belt elongation outfeed 2
   5: XIO(iBeltElongationOutfeed2)OTL(oAlarms[4]);
   // Jam detected in infeed
   6: XIO(iJamSensorInfeed)XIC(iBeltRunning)GRT(iJamSensor1Time,1)MOV(iJamSensor1Time,JamSensor1Timer.PRE)[XIO(JamSensor1Timer.DN) TON(JamSensor1Timer,?,?) ,XIC(JamSensor1Timer.DN) OTL(oAlarms[5]) ];
   // Jam detected in outfeed
   7: XIO(iJamSensorOutfeed)XIC(iBeltRunning)GRT(iJamSensor2Time,1)MOV(iJamSensor2Time,JamSensor2Timer.PRE)[XIO(JamSensor2Timer.DN) TON(JamSensor2Timer,?,?) ,XIC(JamSensor2Timer.DN) OTL(oAlarms[6]) ];
   // Belt disengagement
   8: XIO(iBeltDisengagement)OTL(oAlarms[7]);
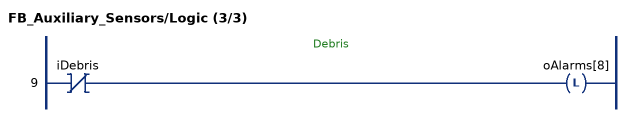
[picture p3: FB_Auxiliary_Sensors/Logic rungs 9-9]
   // Debris
   9: XIO(iDebris)OTL(oAlarms[8]);
END_ROUTINE
END_ADD_ON_INSTRUCTION

ADD_ON_INSTRUCTION FB_FaultCodesTodt   (* revision 1.0, vendor INTRALOX *)
VAR_INPUT
   iCodesDINT : DINT; {required}
END_VAR
VAR_IN_OUT
   oCodesdt : dt_ISC_CAM_FaultCodes; {required}
END_VAR

ROUTINE Logic   (* ladder *)
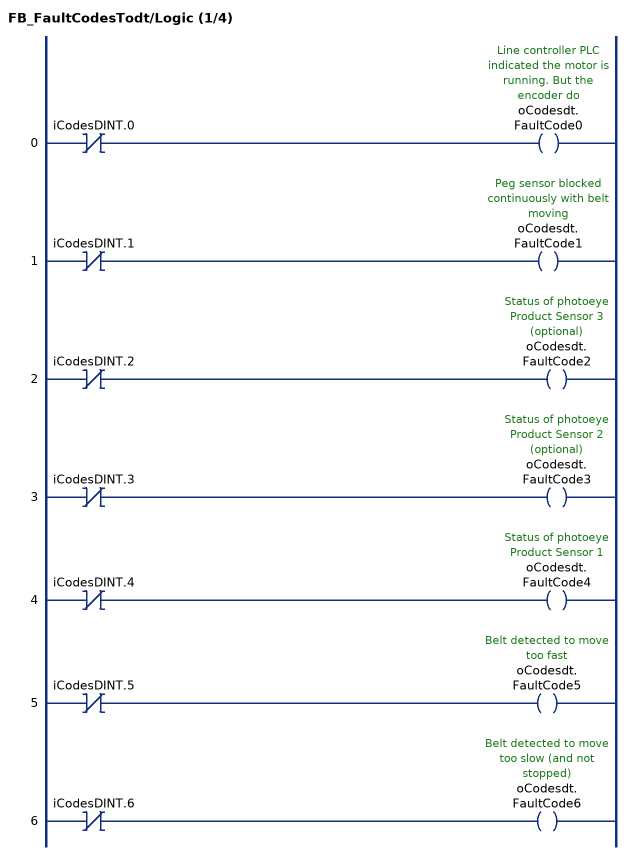
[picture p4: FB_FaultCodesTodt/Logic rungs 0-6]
   0: XIO(iCodesDINT.0)OTE(oCodesdt.FaultCode0);
   1: XIO(iCodesDINT.1)OTE(oCodesdt.FaultCode1);
   2: XIO(iCodesDINT.2)OTE(oCodesdt.FaultCode2);
   3: XIO(iCodesDINT.3)OTE(oCodesdt.FaultCode3);
   4: XIO(iCodesDINT.4)OTE(oCodesdt.FaultCode4);
   5: XIO(iCodesDINT.5)OTE(oCodesdt.FaultCode5);
   6: XIO(iCodesDINT.6)OTE(oCodesdt.FaultCode6);
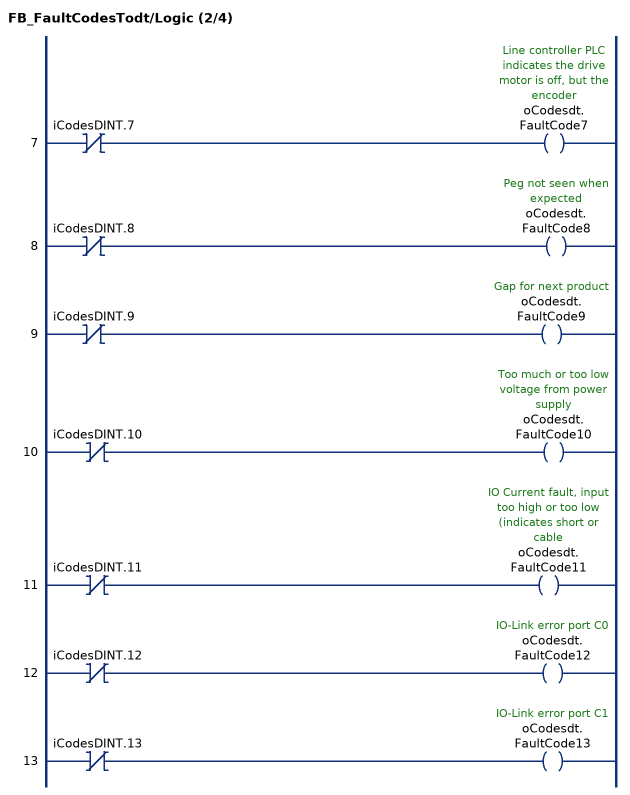
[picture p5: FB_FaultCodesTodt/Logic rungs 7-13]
   7: XIO(iCodesDINT.7)OTE(oCodesdt.FaultCode7);
   8: XIO(iCodesDINT.8)OTE(oCodesdt.FaultCode8);
   9: XIO(iCodesDINT.9)OTE(oCodesdt.FaultCode9);
   10: XIO(iCodesDINT.10)OTE(oCodesdt.FaultCode10);
   11: XIO(iCodesDINT.11)OTE(oCodesdt.FaultCode11);
   12: XIO(iCodesDINT.12)OTE(oCodesdt.FaultCode12);
   13: XIO(iCodesDINT.13)OTE(oCodesdt.FaultCode13);
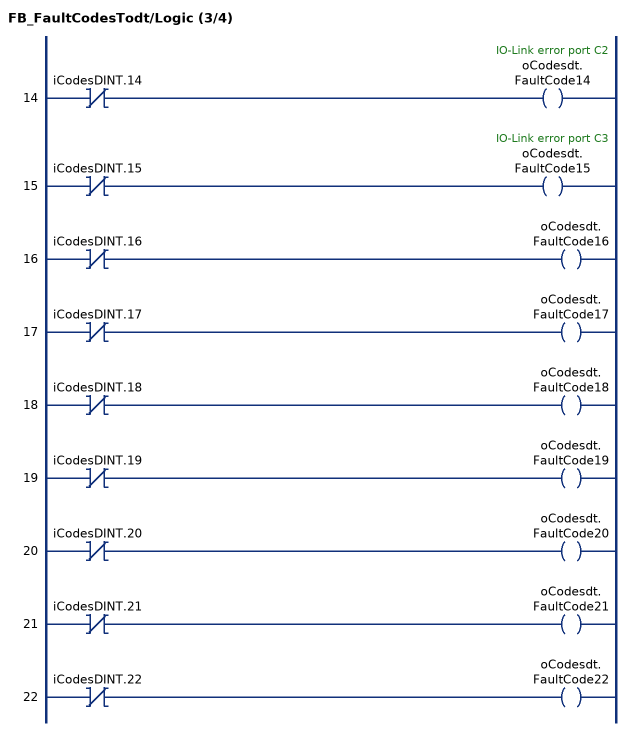
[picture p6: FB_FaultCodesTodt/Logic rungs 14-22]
   14: XIO(iCodesDINT.14)OTE(oCodesdt.FaultCode14);
   15: XIO(iCodesDINT.15)OTE(oCodesdt.FaultCode15);
   16: XIO(iCodesDINT.16)OTE(oCodesdt.FaultCode16);
   17: XIO(iCodesDINT.17)OTE(oCodesdt.FaultCode17);
   18: XIO(iCodesDINT.18)OTE(oCodesdt.FaultCode18);
   19: XIO(iCodesDINT.19)OTE(oCodesdt.FaultCode19);
   20: XIO(iCodesDINT.20)OTE(oCodesdt.FaultCode20);
   21: XIO(iCodesDINT.21)OTE(oCodesdt.FaultCode21);
   22: XIO(iCodesDINT.22)OTE(oCodesdt.FaultCode22);
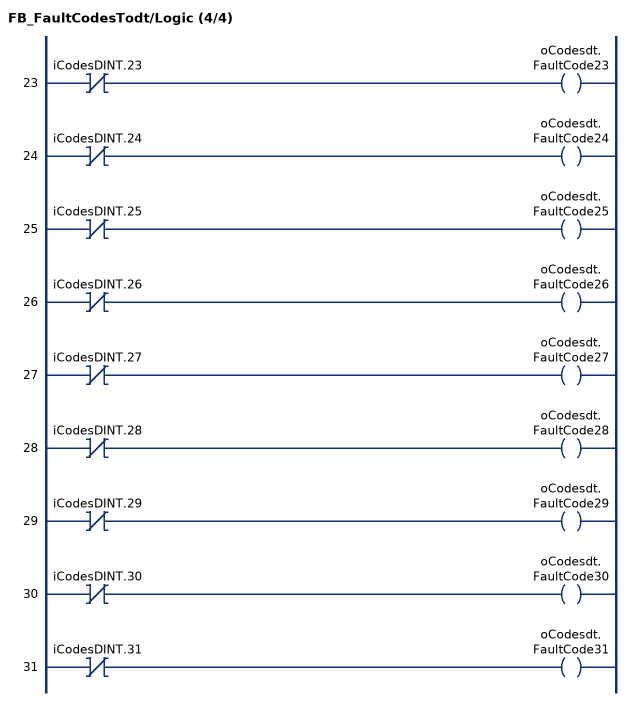
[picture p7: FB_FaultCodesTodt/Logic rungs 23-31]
   23: XIO(iCodesDINT.23)OTE(oCodesdt.FaultCode23);
   24: XIO(iCodesDINT.24)OTE(oCodesdt.FaultCode24);
   25: XIO(iCodesDINT.25)OTE(oCodesdt.FaultCode25);
   26: XIO(iCodesDINT.26)OTE(oCodesdt.FaultCode26);
   27: XIO(iCodesDINT.27)OTE(oCodesdt.FaultCode27);
   28: XIO(iCodesDINT.28)OTE(oCodesdt.FaultCode28);
   29: XIO(iCodesDINT.29)OTE(oCodesdt.FaultCode29);
   30: XIO(iCodesDINT.30)OTE(oCodesdt.FaultCode30);
   31: XIO(iCodesDINT.31)OTE(oCodesdt.FaultCode31);
END_ROUTINE
END_ADD_ON_INSTRUCTION

ADD_ON_INSTRUCTION FB_IO_Conversion   (* revision 1.0, vendor INTRALOX *)
VAR_INPUT
   Input : BOOL; {access None, required}
END_VAR
VAR_IN_OUT
   ArrayIn : INT[48]; {required}
   Inputs : DINT[48]; {required}
   Outputs : DINT[16]; {required}
   ArrayOut : INT[16]; {required}
END_VAR
VAR
   i : INT;
   btdt : FBD_BIT_FIELD_DISTRIBUTE := (Length := 1); {access None}
END_VAR

ROUTINE Logic   (* structured text *)
   If(Input) then
   	For i:=0 to 47 by 1 do
   		btdt.Length:=16;
   		btdt.Target:=0;
   		btdt.DestBit:=0;
   		btdt.SourceBit:=0;
   		btdt.Source:=ArrayIn[i];
   		BTDT(btdt);
   		Inputs[i] := btdt.Dest;
   	end_for;
   else
   	For i:=0 to 15 by 1 do
   		btdt.Target:=0;
   		btdt.Length:=16;
   		btdt.DestBit:=0;
   		btdt.SourceBit:=0;
   		btdt.Source:=Outputs[i];
   		BTDT(btdt);
   		ArrayOut[i]:=btdt.Dest;
   		//COP(tempArray[i],ArrayOut[i],16);
   	end_for;
   end_if;
END_ROUTINE
END_ADD_ON_INSTRUCTION

ADD_ON_INSTRUCTION FB_IO_Todt   (* revision 1.0, vendor INTRALOX *)
VAR_INPUT
   iDINT_IO : DINT; {required}
END_VAR
VAR_IN_OUT
   qIO : dt_ISC_CAM_IOStatus; {required}
END_VAR

ROUTINE Logic   (* ladder *)
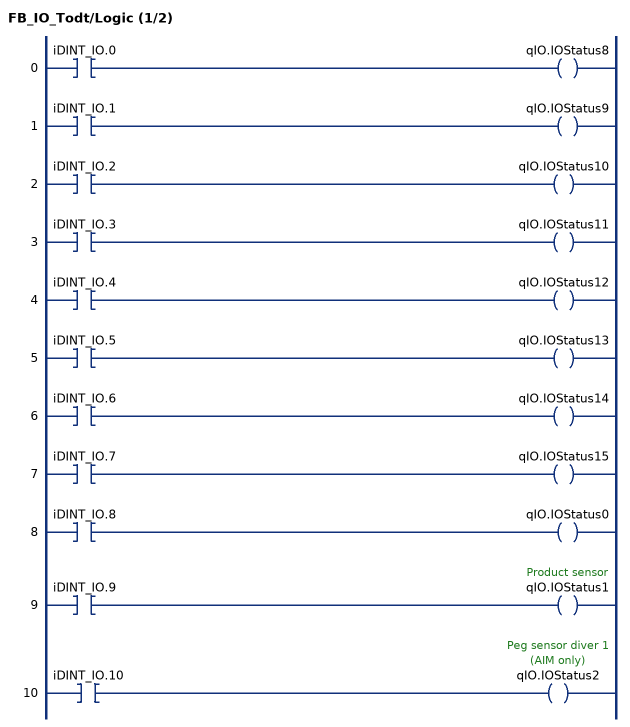
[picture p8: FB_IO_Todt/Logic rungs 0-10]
   0: XIC(iDINT_IO.0)OTE(qIO.IOStatus8);
   1: XIC(iDINT_IO.1)OTE(qIO.IOStatus9);
   2: XIC(iDINT_IO.2)OTE(qIO.IOStatus10);
   3: XIC(iDINT_IO.3)OTE(qIO.IOStatus11);
   4: XIC(iDINT_IO.4)OTE(qIO.IOStatus12);
   5: XIC(iDINT_IO.5)OTE(qIO.IOStatus13);
   6: XIC(iDINT_IO.6)OTE(qIO.IOStatus14);
   7: XIC(iDINT_IO.7)OTE(qIO.IOStatus15);
   8: XIC(iDINT_IO.8)OTE(qIO.IOStatus0);
   9: XIC(iDINT_IO.9)OTE(qIO.IOStatus1);
   10: XIC(iDINT_IO.10)OTE(qIO.IOStatus2);
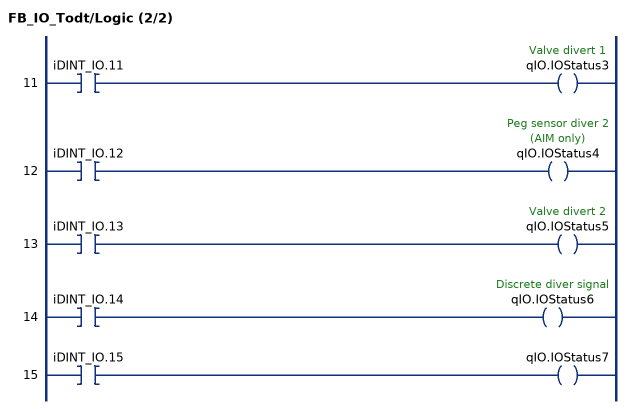
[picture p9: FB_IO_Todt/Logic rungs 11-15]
   11: XIC(iDINT_IO.11)OTE(qIO.IOStatus3);
   12: XIC(iDINT_IO.12)OTE(qIO.IOStatus4);
   13: XIC(iDINT_IO.13)OTE(qIO.IOStatus5);
   14: XIC(iDINT_IO.14)OTE(qIO.IOStatus6);
   15: XIC(iDINT_IO.15)OTE(qIO.IOStatus7);
END_ROUTINE
END_ADD_ON_INSTRUCTION

ADD_ON_INSTRUCTION FB_ISC_Alarms   (* revision 1.0, vendor INTRALOX *)
VAR_INPUT
   iCommsHealthy : BOOL; {access None, required}
END_VAR
VAR_IN_OUT
   iFaults : dt_ISC_CAM_FaultCodes; {required}
   oAlarms : dt_ISC_CAM_Alarms; {required}
END_VAR

ROUTINE Logic   (* ladder *)
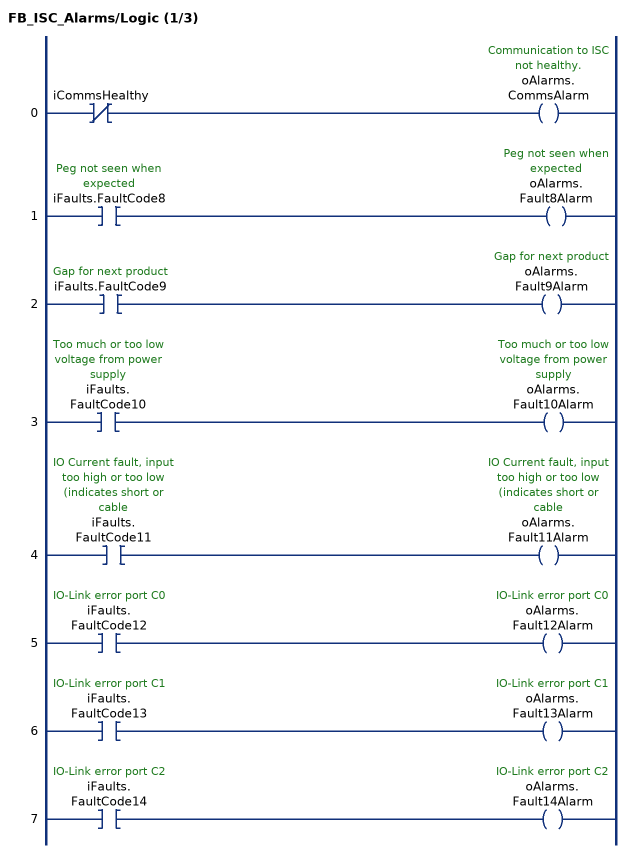
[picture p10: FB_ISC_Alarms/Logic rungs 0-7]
   0: XIO(iCommsHealthy)OTE(oAlarms.CommsAlarm);
   1: XIC(iFaults.FaultCode8)OTE(oAlarms.Fault8Alarm);
   2: XIC(iFaults.FaultCode9)OTE(oAlarms.Fault9Alarm);
   3: XIC(iFaults.FaultCode10)OTE(oAlarms.Fault10Alarm);
   4: XIC(iFaults.FaultCode11)OTE(oAlarms.Fault11Alarm);
   5: XIC(iFaults.FaultCode12)OTE(oAlarms.Fault12Alarm);
   6: XIC(iFaults.FaultCode13)OTE(oAlarms.Fault13Alarm);
   7: XIC(iFaults.FaultCode14)OTE(oAlarms.Fault14Alarm);
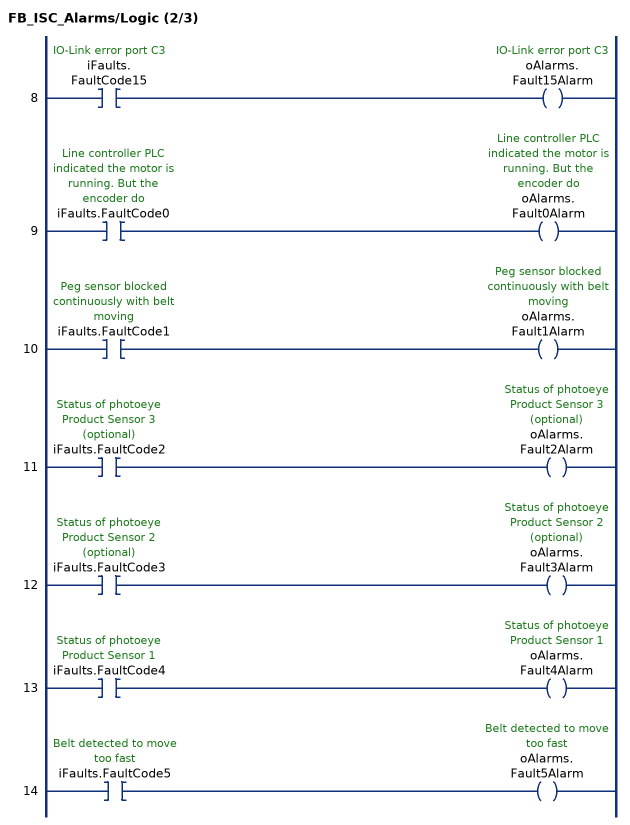
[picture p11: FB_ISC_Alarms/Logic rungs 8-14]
   8: XIC(iFaults.FaultCode15)OTE(oAlarms.Fault15Alarm);
   9: XIC(iFaults.FaultCode0)OTE(oAlarms.Fault0Alarm);
   10: XIC(iFaults.FaultCode1)OTE(oAlarms.Fault1Alarm);
   11: XIC(iFaults.FaultCode2)OTE(oAlarms.Fault2Alarm);
   12: XIC(iFaults.FaultCode3)OTE(oAlarms.Fault3Alarm);
   13: XIC(iFaults.FaultCode4)OTE(oAlarms.Fault4Alarm);
   14: XIC(iFaults.FaultCode5)OTE(oAlarms.Fault5Alarm);
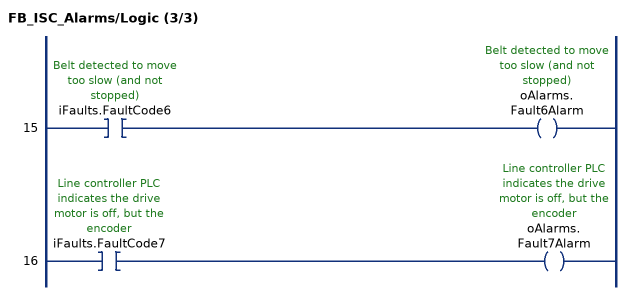
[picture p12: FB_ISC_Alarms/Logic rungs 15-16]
   15: XIC(iFaults.FaultCode6)OTE(oAlarms.Fault6Alarm);
   16: XIC(iFaults.FaultCode7)OTE(oAlarms.Fault7Alarm);
END_ROUTINE
END_ADD_ON_INSTRUCTION

ADD_ON_INSTRUCTION FB_ISC_CAM_Maintenance   (* revision 1.0, vendor INTRALOX *)
VAR_INPUT
   iCounter : DINT; {access None, required}
   iThreshold : DINT; {access None, required}
END_VAR
VAR_OUTPUT
   qCountUntilNextMaintenance : DINT; {access None, required}   // Count until next maintenance [min]
END_VAR
VAR_IN_OUT
   Maintenance : BOOL; {required}
END_VAR
VAR
   LastCount : DINT; {access None}
END_VAR

ROUTINE Logic   (* structured text *)
   IF iThreshold > 0 then
   	IF (iCounter - LastCount) > iThreshold then
   		Maintenance := 1;
   		LastCount := iCounter;
   	end_if;
   	qCountUntilNextMaintenance := iThreshold - (iCounter - LastCount);
   else
   	Maintenance := 0;
   	LastCount :=0;
   	qCountUntilNextMaintenance:=0;
   end_if;
END_ROUTINE
END_ADD_ON_INSTRUCTION

ADD_ON_INSTRUCTION FB_ISCCAM_Comm   (* revision 1.0, vendor INTRALOX *)
// ISC-CAM Comm
VAR_IN_OUT
   iISCCAMReceive : dt_ISCCAM_IO_IN; {required}
   qISCCAMSend : dt_ISCCAM_IO_OUT; {required}
   Parameter : dt_ISCCAM_Parameter; {required}
   qDataCollection : dt_ISCCAM_Datacollection; {required}
   qStatus : dt_ISCCAM_Stat; {required}
   iCommand : dt_ISCCAM_Cmd; {required}
END_VAR
VAR
   IO_Read : FB_ISCCAM_IO_Read; {access None}
   sDataSend : dt_ISC_CAM_Send; {access None}
   sDataReceive : dt_ISC_CAM_Receive; {access None}
   FaultCode : FB_FaultCodesTodt; {access None}
   IOStatus : FB_IO_Todt; {access None}
   sUpTime : FB_2INT_To_DINT; {access None}
   sParameterDataRegisterHighWord : DINT; {access None}
   sParameterData : FB_2INT_To_DINT; {access None}
   IO_Write : FB_ISCCAM_IO_Write; {access None}
   sTempDataCollectionDINT : FB_2INT_To_DINT; {access None}
END_VAR

ROUTINE Logic   (* ladder *)
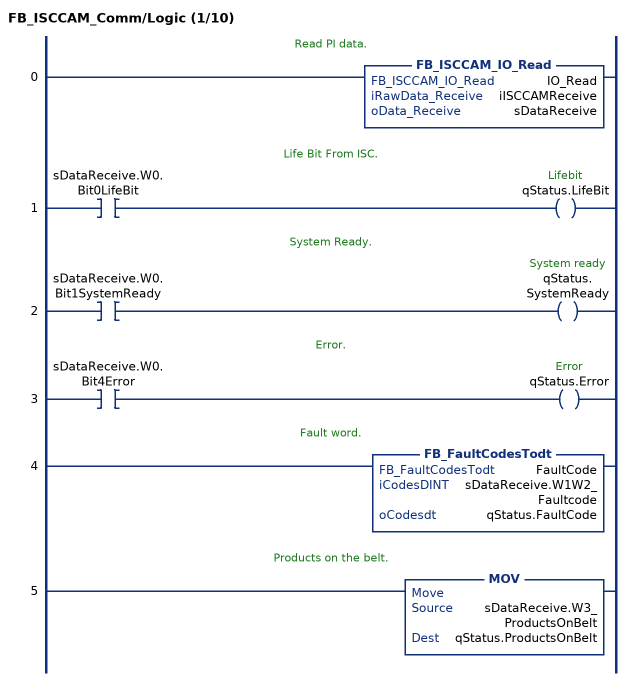
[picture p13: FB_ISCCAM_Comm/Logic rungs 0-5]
   // Read PI data.
   0: FB_ISCCAM_IO_Read(IO_Read,iISCCAMReceive,sDataReceive);
   // Life Bit From ISC.
   1: XIC(sDataReceive.W0.Bit0LifeBit)OTE(qStatus.LifeBit);
   // System Ready.
   2: XIC(sDataReceive.W0.Bit1SystemReady)OTE(qStatus.SystemReady);
   // Error.
   3: XIC(sDataReceive.W0.Bit4Error)OTE(qStatus.Error);
   // Fault word.
   4: FB_FaultCodesTodt(FaultCode,sDataReceive.W1W2_Faultcode,qStatus.FaultCode);
   // Products on the belt.
   5: MOV(sDataReceive.W3_ProductsOnBelt,qStatus.ProductsOnBelt);
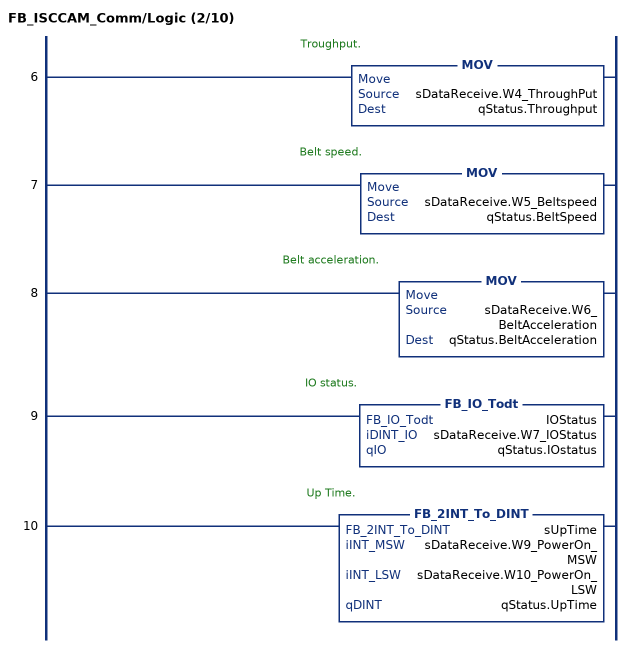
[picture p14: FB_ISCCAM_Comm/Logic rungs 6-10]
   // Troughput.
   6: MOV(sDataReceive.W4_ThroughPut,qStatus.Throughput);
   // Belt speed.
   7: MOV(sDataReceive.W5_Beltspeed,qStatus.BeltSpeed);
   // Belt acceleration.
   8: MOV(sDataReceive.W6_BeltAcceleration,qStatus.BeltAcceleration);
   // IO status.
   9: FB_IO_Todt(IOStatus,sDataReceive.W7_IOStatus,qStatus.IOstatus);
   // Up Time.
   10: FB_2INT_To_DINT(sUpTime,sDataReceive.W9_PowerOn_MSW,sDataReceive.W10_PowerOn_LSW,qStatus.UpTime);
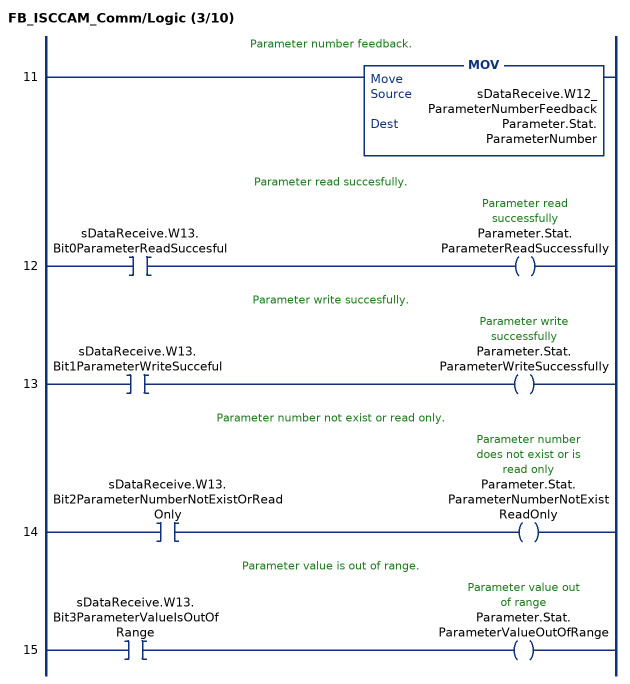
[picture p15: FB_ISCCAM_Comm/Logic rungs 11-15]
   // Parameter number feedback.
   11: MOV(sDataReceive.W12_ParameterNumberFeedback,Parameter.Stat.ParameterNumber);
   // Parameter read succesfully.
   12: XIC(sDataReceive.W13.Bit0ParameterReadSuccesful)OTE(Parameter.Stat.ParameterReadSuccessfully);
   // Parameter write succesfully.
   13: XIC(sDataReceive.W13.Bit1ParameterWriteSucceful)OTE(Parameter.Stat.ParameterWriteSuccessfully);
   // Parameter number not exist or read only.
   14: XIC(sDataReceive.W13.Bit2ParameterNumberNotExistOrReadOnly)OTE(Parameter.Stat.ParameterNumberNotExistReadOnly);
   // Parameter value is out of range.
   15: XIC(sDataReceive.W13.Bit3ParameterValueIsOutOfRange)OTE(Parameter.Stat.ParameterValueOutOfRange);
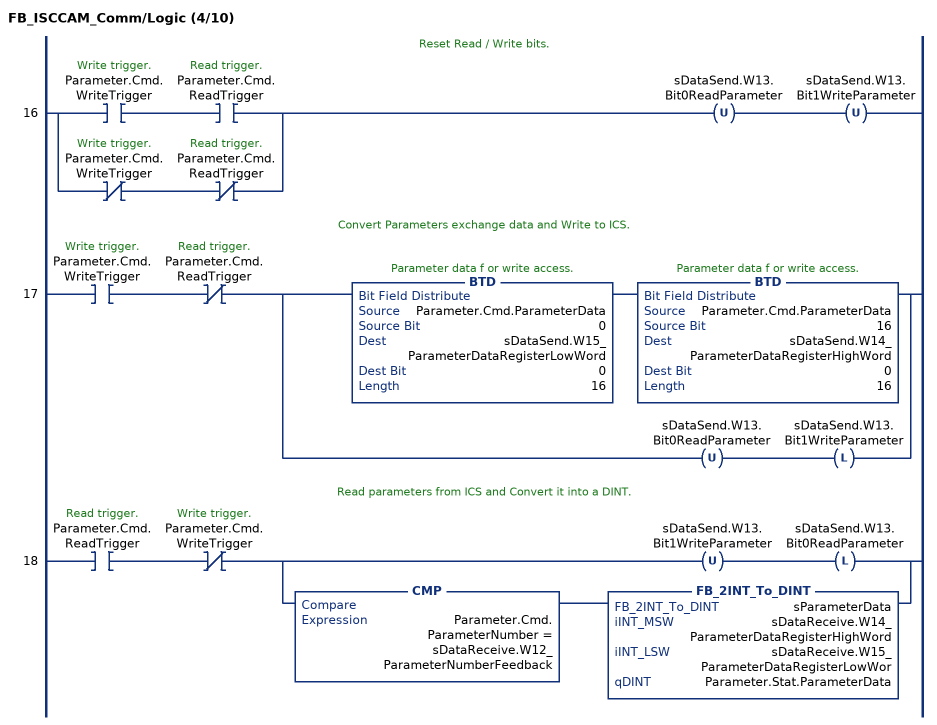
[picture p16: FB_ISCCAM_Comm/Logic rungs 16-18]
   // Reset Read / Write bits.
   16: [XIC(Parameter.Cmd.WriteTrigger) XIC(Parameter.Cmd.ReadTrigger) ,XIO(Parameter.Cmd.WriteTrigger) XIO(Parameter.Cmd.ReadTrigger) ]OTU(sDataSend.W13.Bit0ReadParameter)OTU(sDataSend.W13.Bit1WriteParameter);
   // Convert Parameters exchange data and Write to ICS.
   17: XIC(Parameter.Cmd.WriteTrigger)XIO(Parameter.Cmd.ReadTrigger)[BTD(Parameter.Cmd.ParameterData,0,sDataSend.W15_ParameterDataRegisterLowWord,0,16) BTD(Parameter.Cmd.ParameterData,16,sDataSend.W14_ParameterDataRegisterHighWord,0,16) ,OTU(sDataSend.W13.Bit0ReadParameter) OTL(sDataSend.W13.Bit1WriteParameter) ];
   // Read parameters from ICS and Convert it into a DINT.
   18: XIC(Parameter.Cmd.ReadTrigger)XIO(Parameter.Cmd.WriteTrigger)[OTU(sDataSend.W13.Bit1WriteParameter) OTL(sDataSend.W13.Bit0ReadParameter) ,CMP(Parameter.Cmd.ParameterNumber = sDataReceive.W12_ParameterNumberFeedback) FB_2INT_To_DINT(sParameterData,sDataReceive.W14_ParameterDataRegisterHighWord,sDataReceive.W15_ParameterDataRegisterLowWor,Parameter.Stat.ParameterData) ];
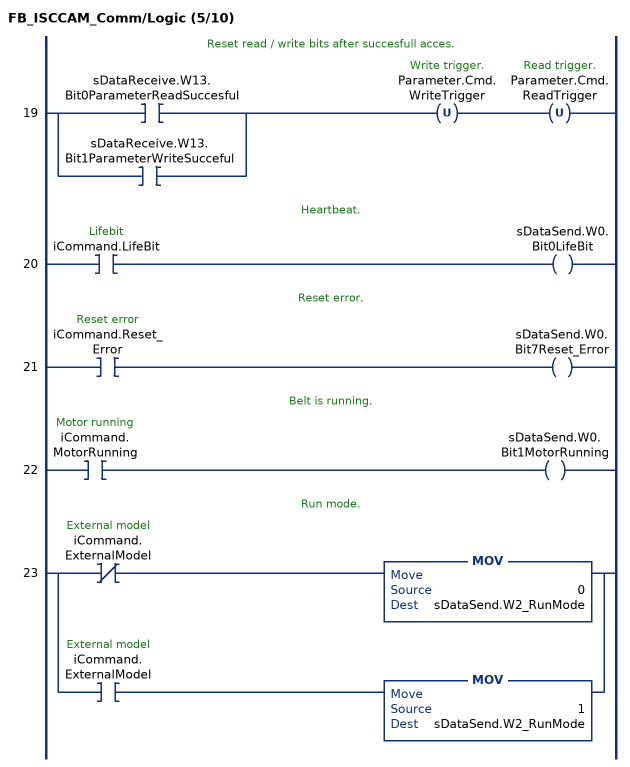
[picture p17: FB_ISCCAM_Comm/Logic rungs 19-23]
   // Reset read / write bits after succesfull acces.
   19: [XIC(sDataReceive.W13.Bit0ParameterReadSuccesful) ,XIC(sDataReceive.W13.Bit1ParameterWriteSucceful) ]OTU(Parameter.Cmd.WriteTrigger)OTU(Parameter.Cmd.ReadTrigger);
   // Heartbeat.
   20: XIC(iCommand.LifeBit)OTE(sDataSend.W0.Bit0LifeBit);
   // Reset error.
   21: XIC(iCommand.Reset_Error)OTE(sDataSend.W0.Bit7Reset_Error);
   // Belt is running.
   22: XIC(iCommand.MotorRunning)OTE(sDataSend.W0.Bit1MotorRunning);
   // Run mode.
   23: [XIO(iCommand.ExternalModel) MOV(0,sDataSend.W2_RunMode) ,XIC(iCommand.ExternalModel) MOV(1,sDataSend.W2_RunMode) ];
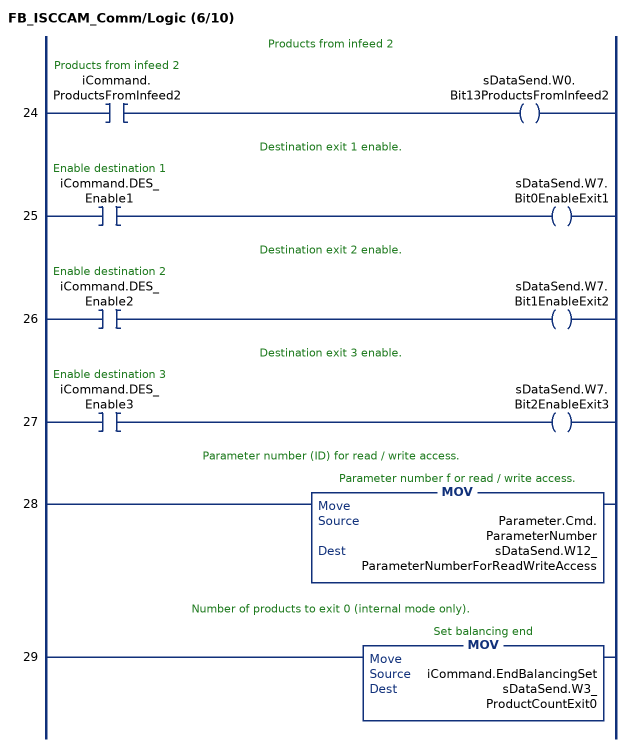
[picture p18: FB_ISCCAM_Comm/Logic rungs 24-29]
   // Products from infeed 2
   24: XIC(iCommand.ProductsFromInfeed2)OTE(sDataSend.W0.Bit13ProductsFromInfeed2);
   // Destination exit 1 enable.
   25: XIC(iCommand.DES_Enable1)OTE(sDataSend.W7.Bit0EnableExit1);
   // Destination exit 2 enable.
   26: XIC(iCommand.DES_Enable2)OTE(sDataSend.W7.Bit1EnableExit2);
   // Destination exit 3 enable.
   27: XIC(iCommand.DES_Enable3)OTE(sDataSend.W7.Bit2EnableExit3);
   // Parameter number (ID) for read / write access.
   28: MOV(Parameter.Cmd.ParameterNumber,sDataSend.W12_ParameterNumberForReadWriteAccess);
   // Number of products to exit 0 (internal mode only).
   29: MOV(iCommand.EndBalancingSet,sDataSend.W3_ProductCountExit0);
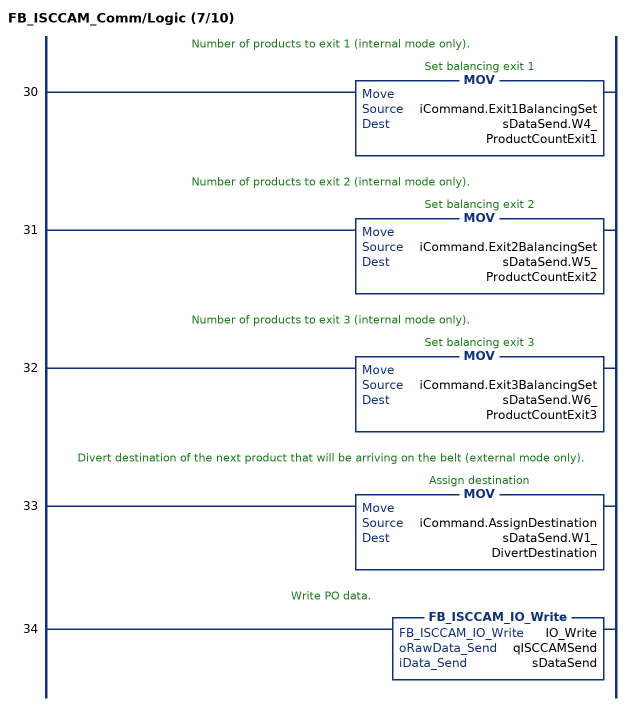
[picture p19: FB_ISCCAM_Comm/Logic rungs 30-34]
   // Number of products to exit 1 (internal mode only).
   30: MOV(iCommand.Exit1BalancingSet,sDataSend.W4_ProductCountExit1);
   // Number of products to exit 2 (internal mode only).
   31: MOV(iCommand.Exit2BalancingSet,sDataSend.W5_ProductCountExit2);
   // Number of products to exit 3 (internal mode only).
   32: MOV(iCommand.Exit3BalancingSet,sDataSend.W6_ProductCountExit3);
   // Divert destination of the next product that will be arriving on the belt (external mode only).
   33: MOV(iCommand.AssignDestination,sDataSend.W1_DivertDestination);
   // Write PO data.
   34: FB_ISCCAM_IO_Write(IO_Write,qISCCAMSend,sDataSend);
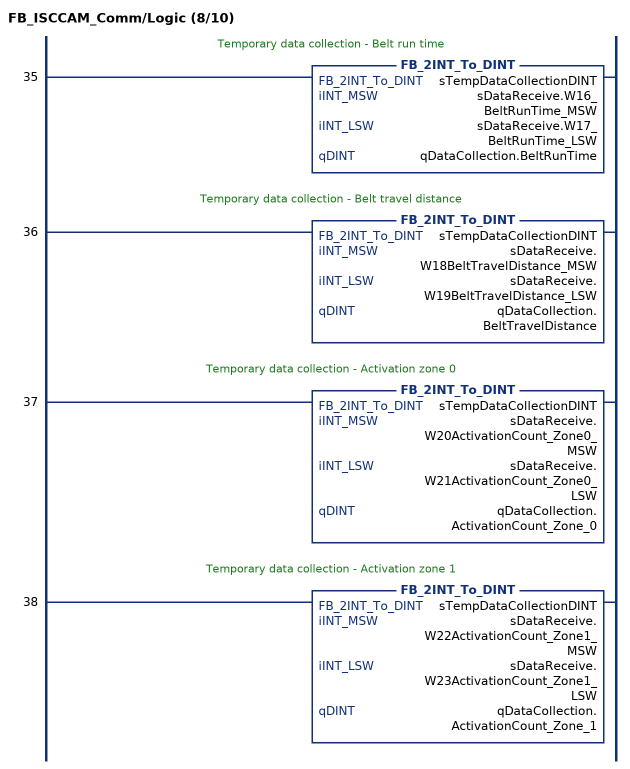
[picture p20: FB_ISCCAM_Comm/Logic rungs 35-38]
   // Temporary data collection - Belt run time
   35: FB_2INT_To_DINT(sTempDataCollectionDINT,sDataReceive.W16_BeltRunTime_MSW,sDataReceive.W17_BeltRunTime_LSW,qDataCollection.BeltRunTime);
   // Temporary data collection - Belt travel distance
   36: FB_2INT_To_DINT(sTempDataCollectionDINT,sDataReceive.W18BeltTravelDistance_MSW,sDataReceive.W19BeltTravelDistance_LSW,qDataCollection.BeltTravelDistance);
   // Temporary data collection - Activation zone 0
   37: FB_2INT_To_DINT(sTempDataCollectionDINT,sDataReceive.W20ActivationCount_Zone0_MSW,sDataReceive.W21ActivationCount_Zone0_LSW,qDataCollection.ActivationCount_Zone_0);
   // Temporary data collection - Activation zone 1
   38: FB_2INT_To_DINT(sTempDataCollectionDINT,sDataReceive.W22ActivationCount_Zone1_MSW,sDataReceive.W23ActivationCount_Zone1_LSW,qDataCollection.ActivationCount_Zone_1);
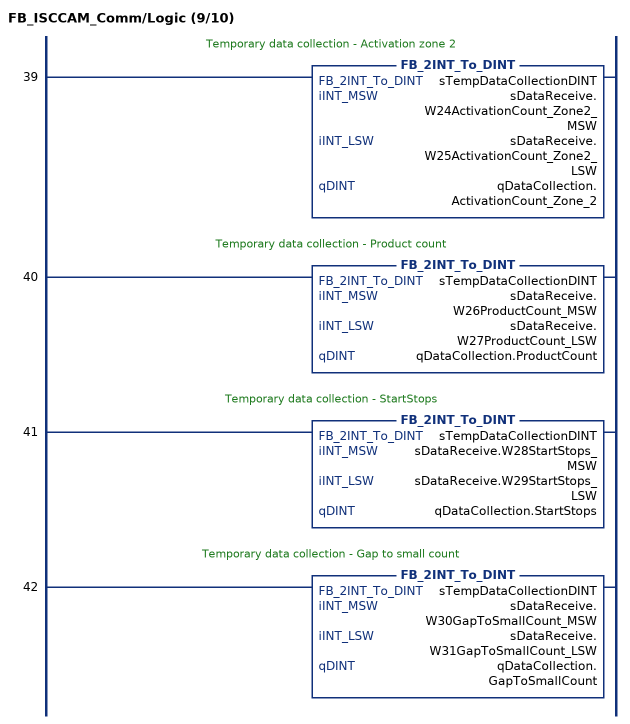
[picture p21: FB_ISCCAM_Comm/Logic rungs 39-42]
   // Temporary data collection - Activation zone 2
   39: FB_2INT_To_DINT(sTempDataCollectionDINT,sDataReceive.W24ActivationCount_Zone2_MSW,sDataReceive.W25ActivationCount_Zone2_LSW,qDataCollection.ActivationCount_Zone_2);
   // Temporary data collection - Product count
   40: FB_2INT_To_DINT(sTempDataCollectionDINT,sDataReceive.W26ProductCount_MSW,sDataReceive.W27ProductCount_LSW,qDataCollection.ProductCount);
   // Temporary data collection - StartStops
   41: FB_2INT_To_DINT(sTempDataCollectionDINT,sDataReceive.W28StartStops_MSW,sDataReceive.W29StartStops_LSW,qDataCollection.StartStops);
   // Temporary data collection - Gap to small count
   42: FB_2INT_To_DINT(sTempDataCollectionDINT,sDataReceive.W30GapToSmallCount_MSW,sDataReceive.W31GapToSmallCount_LSW,qDataCollection.GapToSmallCount);
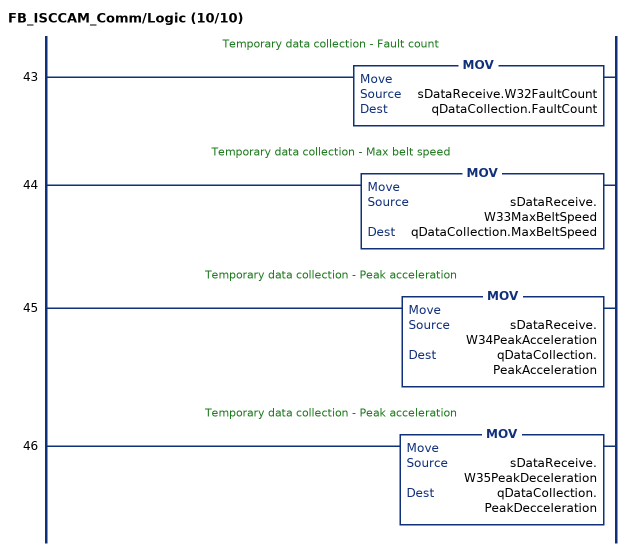
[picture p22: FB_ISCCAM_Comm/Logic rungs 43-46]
   // Temporary data collection - Fault count
   43: MOV(sDataReceive.W32FaultCount,qDataCollection.FaultCount);
   // Temporary data collection - Max belt speed
   44: MOV(sDataReceive.W33MaxBeltSpeed,qDataCollection.MaxBeltSpeed);
   // Temporary data collection - Peak acceleration
   45: MOV(sDataReceive.W34PeakAcceleration,qDataCollection.PeakAcceleration);
   // Temporary data collection - Peak acceleration
   46: MOV(sDataReceive.W35PeakDeceleration,qDataCollection.PeakDecceleration);
END_ROUTINE
END_ADD_ON_INSTRUCTION
